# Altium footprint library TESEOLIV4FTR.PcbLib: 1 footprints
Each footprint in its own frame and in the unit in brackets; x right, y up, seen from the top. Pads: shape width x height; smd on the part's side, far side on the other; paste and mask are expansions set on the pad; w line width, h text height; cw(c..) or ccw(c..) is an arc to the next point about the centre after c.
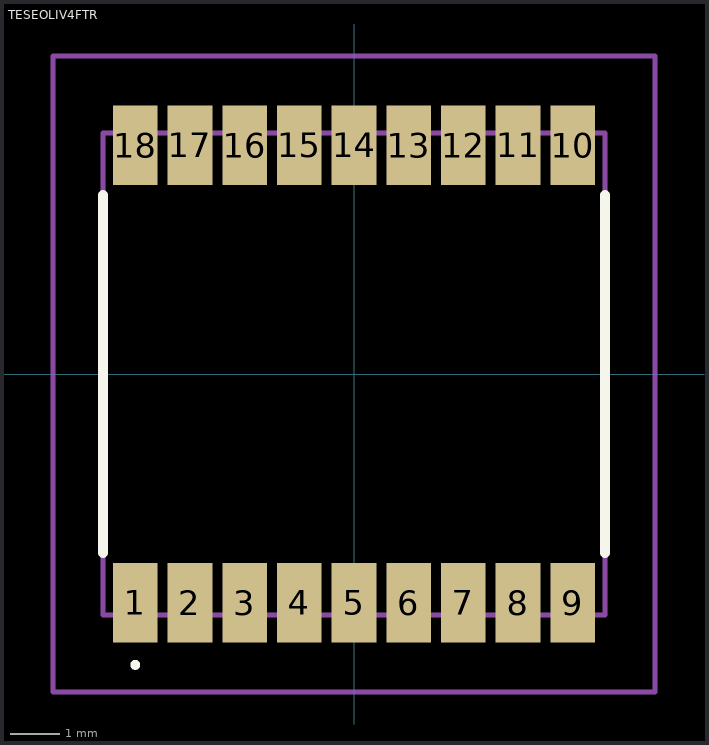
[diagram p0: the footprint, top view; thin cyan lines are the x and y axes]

## TESEOLIV4FTR [mm]
pads (18):
  rect 0.9x1.6 smd: 1(-4.4,-4.6) 2(-3.3,-4.6) 3(-2.2,-4.6) 4(-1.1,-4.6) 5(0,-4.6) 6(1.1,-4.6) 7(2.2,-4.6) 8(3.3,-4.6) 9(4.4,-4.6) 10(4.4,4.6) 11(3.3,4.6) 12(2.2,4.6) 13(1.1,4.6) 14(0,4.6) 15(-1.1,4.6) 16(-2.2,4.6) 17(-3.3,4.6) 18(-4.4,4.6)
Top Overlay:
  lines w0.1: -4.4,-5.9 cw(c-4.4,-5.85) -4.4,-5.8 ; -4.4,-5.9 -4.4,-5.9 ; -4.4,-5.9 ccw(c-4.4,-5.85) -4.4,-5.8 ; -4.4,-5.8 -4.4,-5.8
  lines w0.2: -5.05,-3.6 -5.05,3.6 ; 5.05,-3.6 5.05,3.6
Mechanical 15:
  lines w0.1: -5.05,-4.85 5.05,-4.85 5.05,4.85 -5.05,4.85 -5.05,-4.85
Mechanical 20:
  lines w0.1: -6.05,-6.4 6.05,-6.4 6.05,6.4 -6.05,6.4 -6.05,-6.4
